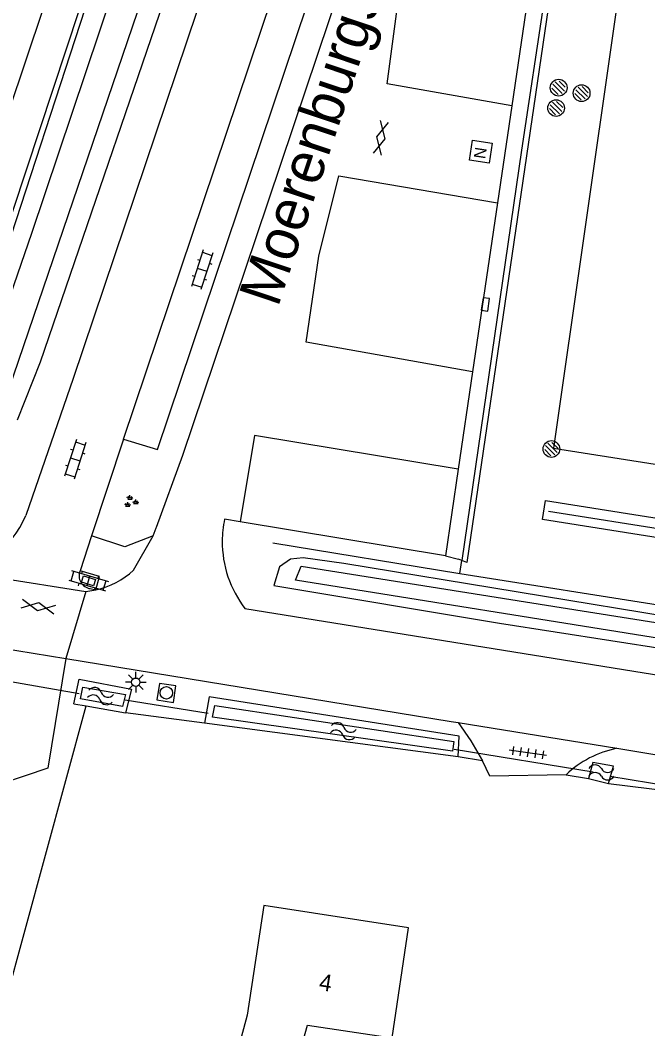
# Model space of a CAD drawing. Extents: x 135999 to 138000, y 396000 to 398501.
# Drawn here: x 136337.3 to 136374.9, y 396332.1 to 396392.4 of the extents above; entities that cross this region are included whole.
import ezdxf

# ---------------------------------------------------------------- set-up
doc = ezdxf.new("R2010")
doc.units = 0
for name, color, linetype in [('bs-afsc-ballenvanger', 7, 'Continuous'), ('bs-afsc-belijning', 7, 'Continuous'), ('bs-afsc-hekwerk laag', 7, 'Continuous'), ('bs-symb-cornervlag', 7, 'Continuous'), ('bs-symb-magneetklep', 7, 'Continuous'), ('bs-symb-sproeier', 7, 'Continuous'), ('gg-afsc-draadraster', 7, 'Continuous'), ('gg-afsc-hekwerk', 7, 'Continuous'), ('gg-afsc-lijn draadraster', 7, 'Continuous'), ('gg-anno-huisnummerreeks BGT', 7, 'Continuous'), ('gg-anno-openbare ruimte label', 7, 'Continuous'), ('gg-bbg-hoofdgebouw', 7, 'Continuous'), ('gg-knt-verharding', 7, 'Continuous'), ('gg-knt-verharding nz', 7, 'Continuous'), ('gg-kntw-bovenkant insteek waterloop', 7, 'Continuous'), ('gg-kntw-waterlijn', 7, 'Continuous'), ('gg-kwrk-duiker nz buis', 7, 'Continuous'), ('gt-grn-groengrens', 7, 'Continuous'), ('gt-grn-weggrens', 7, 'Continuous'), ('gt-symb-gesloten verharding', 7, 'Continuous'), ('gt-symb-groenvak', 7, 'Continuous'), ('gt-symb-klinker verharding', 7, 'Continuous'), ('gt-symb-kolk', 7, 'Continuous'), ('gt-symb-kolk center center', 7, 'Continuous'), ('gt-symb-lichtmast', 7, 'Continuous'), ('gt-symb-nortonput', 7, 'Continuous'), ('gt-symb-rioolschacht', 7, 'Continuous'), ('gt-symb-tegel verharding', 7, 'Continuous'), ('gt-symb-watersymbool', 7, 'Continuous')]:
    doc.layers.add(name, color=color, linetype=linetype)

# ---------------------------------------------------------------- blocks, each defined once
blk = doc.blocks.new('gt0-KL1')
at = {"layer": 'gt-symb-klinker verharding'}
for p, q in [((-1.15, 0.3), (1.15, 0.3)), ((-1, -0.3), (-1, 0.3)), ((-0.5, 0.3), (-0.5, 0.45)), ((0, -0.3), (0, 0.3)), ((0.5, 0.3), (0.5, 0.45)), ((1, -0.3), (1, 0.3)), ((-1.15, -0.3), (1.15, -0.3)), ((-0.5, -0.45), (-0.5, -0.3)), ((0.5, -0.45), (0.5, -0.3))]:
    blk.add_line(p, q, dxfattribs=at)
blk = doc.blocks.new('gt0-GESVH1')
at = {"layer": 'gt-symb-gesloten verharding'}
for p, q in [((-0.992, -0.261), (0.008, 0.239)), ((0.008, -0.261), (-0.992, 0.239)), ((0.008, 0.239), (1.008, -0.261)), ((1.008, 0.239), (0.008, -0.261))]:
    blk.add_line(p, q, dxfattribs=at)
blk = doc.blocks.new('gt0-NPUT')
at = {"layer": 'gt-symb-nortonput'}
blk.add_lwpolyline([(-0.566, -0.608), (-0.566, 0.592), (0.634, 0.592), (0.634, -0.608)], close=True, dxfattribs=at)
blk.add_text('N', height=0.7, dxfattribs=at).set_placement((-0.221, -0.381))
blk = doc.blocks.new('gt0-KOLK')
at = {"layer": 'gt-symb-kolk'}
blk.add_lwpolyline([(0, 0), (0.375, 0), (0.375, 0.4), (-0.375, 0.4), (-0.375, 0), (0, 0)], dxfattribs=at)
blk = doc.blocks.new('bs0-CORNVLG')
at = {"layer": 'bs-symb-cornervlag'}
for p, q in [((-0.345, 0.203), (0.203, -0.345)), ((-0.212, 0.354), (0.345, -0.203)), ((0.025, 0.399), (0.399, 0.025)), ((-0.399, -0.025), (-0.025, -0.399))]:
    blk.add_line(p, q, dxfattribs=at)
blk.add_circle((0, 0), 0.5, dxfattribs=at)
blk = doc.blocks.new('BS0-MAGNKLP')
at = {"layer": 'bs-symb-magneetklep'}
for p, q in [((-0.345, 0.203), (0.203, -0.345)), ((-0.212, 0.354), (0.345, -0.203)), ((0.025, 0.399), (0.399, 0.025)), ((-0.399, -0.025), (-0.025, -0.399))]:
    blk.add_line(p, q, dxfattribs=at)
blk.add_circle((0, 0), 0.5, dxfattribs=at)
blk = doc.blocks.new('bs0-SPROEIER')
at = {"layer": 'bs-symb-sproeier'}
for p, q in [((-0.345, 0.203), (0.203, -0.345)), ((-0.212, 0.354), (0.345, -0.203)), ((0.025, 0.399), (0.399, 0.025)), ((-0.399, -0.025), (-0.025, -0.399))]:
    blk.add_line(p, q, dxfattribs=at)
blk.add_circle((0, 0), 0.5, dxfattribs=at)
blk = doc.blocks.new('gt0-KOLKCC')
at = {"layer": 'gt-symb-kolk center center'}
blk.add_lwpolyline([(-0.375, 0.2), (0.375, 0.2), (0.375, -0.2), (-0.375, -0.2)], close=True, dxfattribs=at)
blk = doc.blocks.new('gt0-GRVAK')
at = {"layer": 'gt-symb-groenvak'}
for p, q in [((-0.11, 0.189), (-0.228, 0.24)), ((-0.182, 0.153), (0.088, 0.153)), ((-0.091, 0.211), (-0.156, 0.322)), ((-0.047, 0.214), (-0.047, 0.393)), ((-0.004, 0.211), (0.061, 0.322)), ((0.015, 0.189), (0.133, 0.24)), ((0.262, -0.052), (0.197, 0.059)), ((0.305, -0.049), (0.305, 0.13)), ((0.349, -0.052), (0.414, 0.059)), ((-0.245, -0.228), (-0.363, -0.177)), ((-0.318, -0.264), (-0.047, -0.264)), ((-0.226, -0.206), (-0.291, -0.095)), ((-0.183, -0.203), (-0.183, -0.024)), ((-0.139, -0.206), (-0.074, -0.095)), ((-0.12, -0.228), (-0.002, -0.177)), ((0.243, -0.074), (0.125, -0.023)), ((0.17, -0.11), (0.441, -0.11)), ((0.368, -0.074), (0.486, -0.023))]:
    blk.add_line(p, q, dxfattribs=at)
blk = doc.blocks.new('gt0-TEG1')
at = {"layer": 'gt-symb-tegel verharding'}
for p, q in [((-1.125, 0), (1.125, 0)), ((-0.9, -0.25), (-0.9, 0.25)), ((-0.45, -0.25), (-0.45, 0.25)), ((0, -0.25), (0, 0.25)), ((0.45, -0.25), (0.45, 0.25)), ((0.9, -0.25), (0.9, 0.25))]:
    blk.add_line(p, q, dxfattribs=at)
blk = doc.blocks.new('gt0-WA')
at = {"layer": 'gt-symb-watersymbool'}
for centre, start, end in [((-0.323, 0.022), 28.07249, 151.92751), ((0.427, 0.422), 208.07248, 331.92751), ((-0.323, -0.428), 28.07249, 151.92751), ((0.427, -0.028), 208.07248, 331.92751)]:
    blk.add_arc(centre, 0.425, start, end, dxfattribs=at)
blk = doc.blocks.new('gt0-RS')
at = {"layer": 'gt-symb-rioolschacht'}
blk.add_lwpolyline([(-0.5, -0.5), (0.5, -0.5), (0.5, 0.5), (-0.5, 0.5)], close=True, dxfattribs=at)
blk.add_circle((0, 0), 0.375, dxfattribs=at)
blk = doc.blocks.new('gt0-LMAST')
at = {"layer": 'gt-symb-lichtmast'}
for p, q in [((-0.005, 0.246), (-0.005, 0.621)), ((-0.182, 0.173), (-0.447, 0.438)), ((0.172, 0.173), (0.437, 0.438)), ((-0.255, -0.004), (-0.63, -0.004)), ((-0.182, -0.181), (-0.447, -0.446)), ((-0.005, -0.254), (-0.005, -0.629)), ((0.437, -0.446), (0.172, -0.181)), ((0.245, -0.004), (0.62, -0.004))]:
    blk.add_line(p, q, dxfattribs=at)
blk.add_circle((-0.005, -0.004), 0.25, dxfattribs=at)

msp = doc.modelspace()

# ---------------------------------------------------------------- linework, layer by layer
at = {"layer": 'bs-afsc-ballenvanger'}
msp.add_line((136369.803, 396400.981), (136367.356, 396384.632), dxfattribs=at)
at = {"layer": 'bs-afsc-belijning'}
msp.add_lwpolyline([(136378.402, 396430.675), (136369.254, 396366.811), (136467.634, 396351.324), (136477.189, 396415.479), (136378.402, 396430.675)], dxfattribs=at)
at = {"layer": 'bs-afsc-hekwerk laag'}
msp.add_line((136368.955, 396363.037), (136408.299, 396356.817), dxfattribs=at)
at = {"layer": 'gg-afsc-draadraster'}
msp.add_lwpolyline([(136316.473, 396371.328), (136328.234, 396369.556), (136330.28, 396369.629), (136330.708, 396369.968), (136331.376, 396371.258), (136340.864, 396399.461), (136351.225, 396430.408), (136351.461, 396433.69), (136351.292, 396436.582), (136350.934, 396439.456), (136350.145, 396442.255), (136346.234, 396453.511)], dxfattribs=at)
at = {"layer": 'gg-afsc-hekwerk'}
for p, q in [((136369.803, 396400.981), (136367.356, 396384.632)), ((136367.356, 396384.632), (136363.778, 396360.091)), ((136368.955, 396363.037), (136408.299, 396356.817)), ((136352.472, 396361.146), (136363.662, 396359.3)), ((136363.662, 396359.3), (136363.778, 396360.091)), ((136363.662, 396359.3), (136422.054, 396350.081)), ((136336.431, 396333.512), (136341.298, 396351.385)), ((136336.431, 396333.512), (136341.298, 396351.385))]:
    msp.add_line(p, q, dxfattribs=at)
at = {"layer": 'gg-afsc-lijn draadraster'}
msp.add_lwpolyline([(136315.547, 396371.468), (136328.234, 396369.556), (136330.28, 396369.629), (136330.708, 396369.968), (136331.376, 396371.258), (136340.864, 396399.461), (136351.225, 396430.408), (136351.461, 396433.69), (136351.292, 396436.582), (136350.934, 396439.456), (136350.145, 396442.255), (136346.234, 396453.511), (136318.123, 396443.287), (136292.891, 396434.111)], dxfattribs=at)
at = {"layer": 'gg-bbg-hoofdgebouw'}
for points in [[(136360.59, 396338.11), (136351.93, 396339.45), (136350.92, 396332.88), (136349.45, 396327.4), (136345.05, 396328.65)], [(136353.15, 396305.594), (136358.514, 396324.838), (136352.897, 396326.435), (136354.542, 396332.282), (136359.606, 396331.525), (136360.59, 396338.11)]]:
    msp.add_lwpolyline(points, dxfattribs=at)
at = {"layer": 'gg-knt-verharding'}
for p, q in [((136366.763, 396387.286), (136365.91, 396381.49)), ((136365.91, 396381.49), (136364.42, 396371.371)), ((136364.42, 396371.371), (136363.562, 396365.543)), ((136343.534, 396367.348), (136341.622, 396361.556)), ((136363.562, 396365.543), (136362.799, 396360.358)), ((136350.513, 396362.395), (136349.575, 396362.551)), ((136362.799, 396360.358), (136350.513, 396362.395)), ((136345.305, 396361.555), (136345.481, 396362.033)), ((136345.481, 396362.033), (136345.494, 396362.069)), ((136341.622, 396361.556), (136340.932, 396359.464)), ((136344.124, 396359.512), (136345.305, 396361.555)), ((136362.799, 396360.358), (136363.573, 396360.173)), ((136363.778, 396360.091), (136363.573, 396360.173)), ((136332.689, 396359.581), (136341.283, 396358.222)), ((136341.283, 396358.222), (136341.868, 396358.331)), ((136341.542, 396358.4), (136341.868, 396358.331)), ((136336.158, 396354.863), (136340.08, 396354.222)), ((136363.552, 396350.388), (136373.06, 396348.846)), ((136373.06, 396348.846), (136377.113, 396348.189))]:
    msp.add_line(p, q, dxfattribs=at)
for points in [[(136351.498, 396379.478), (136369.019, 396431.609), (136369.594, 396433.811), (136370.02, 396436.047)], [(136444.613, 396425.394), (136483.556, 396419.306), (136483.359, 396418.079), (136375.706, 396435.008), (136375.007, 396434.485), (136364.072, 396359.973), (136363.778, 396360.091)], [(136360.876, 396431.432), (136340.51, 396370.978), (136337.676, 396362.774)], [(136343.534, 396367.348), (136345.554, 396366.721), (136366.957, 396430.277)], [(136371.188, 396417.185), (136368.898, 396401.792), (136366.763, 396387.286)], [(136345.494, 396362.069), (136347.082, 396366.382), (136351.498, 396379.478)], [(136368.608, 396362.538), (136368.781, 396363.669), (136407.694, 396357.508), (136407.822, 396358.302), (136413.208, 396357.336), (136413.118, 396356.595), (136420.535, 396355.482), (136420.612, 396355.977), (136426.028, 396354.998), (136425.966, 396354.621), (136464.689, 396348.467), (136464.493, 396347.39), (136425.771, 396353.51), (136425.75, 396353.01), (136420.241, 396353.979), (136420.294, 396354.342), (136368.608, 396362.538)], [(136341.868, 396358.331), (136342.098, 396359.126), (136340.932, 396359.464)], [(136350.799, 396357.209), (136385.344, 396351.652), (136429.378, 396344.684), (136470.073, 396338.203), (136496.298, 396334.058), (136506.466, 396332.412)], [(136340.08, 396354.222), (136339.007, 396347.648), (136334.85, 396346.267)], [(136340.08, 396354.222), (136363.13, 396350.456), (136363.552, 396350.388)], [(136363.552, 396350.388), (136364.32, 396349.287), (136365.008, 396348.091)], [(136370.012, 396347.265), (136365.455, 396347.17), (136365.008, 396348.091)]]:
    msp.add_lwpolyline(points, dxfattribs=at)
for centre, radius, start, end in [((136332.948, 396364.667), 5.093, 267.08221, 338.17779), ((136355.998, 396361.217), 6.56, 168.26644, 179.72929), ((136356.004, 396361.212), 6.566, 179.68338, 217.56061), ((136341.646, 396359.167), 0.774, 157.40271, 262.2493), ((136340.963, 396362.805), 4.565, 281.43638, 313.82709), ((136374.316, 396342.695), 6.278, 101.54457, 133.28704)]:
    msp.add_arc(centre, radius, start, end, dxfattribs=at)
at = {"layer": 'gg-knt-verharding nz'}
for p, q in [((136343.534, 396367.348), (136364.941, 396430.964)), ((136356.414, 396383.109), (136365.91, 396381.49))]:
    msp.add_line(p, q, dxfattribs=at)
for points in [[(136366.763, 396387.286), (136359.308, 396388.614), (136359.993, 396393.706), (136362.489, 396393.37), (136364.718, 396408.071)], [(136364.42, 396371.371), (136354.458, 396373.14), (136355.217, 396378.298), (136356.414, 396383.109)], [(136363.562, 396365.543), (136351.371, 396367.565), (136350.513, 396362.395)]]:
    msp.add_lwpolyline(points, dxfattribs=at)
at = {"layer": 'gg-kntw-bovenkant insteek waterloop'}
for p, q in [((136340.565, 396351.515), (136341.298, 396351.385)), ((136341.298, 396351.385), (136343.647, 396350.967)), ((136363.55, 396348.332), (136348.38, 396350.341)), ((136371.358, 396347.043), (136372.552, 396346.737))]:
    msp.add_line(p, q, dxfattribs=at)
for points in [[(136353.609, 396430.235), (136352.783, 396426.924), (136344.17, 396402.155), (136333.229, 396368.651)], [(136337.187, 396368.492), (136338.555, 396371.978), (136347.487, 396398.048), (136356.535, 396425.934)], [(136354.29, 396360.247), (136353.513, 396360.156), (136352.86, 396359.695), (136352.516, 396358.594), (136366.034, 396356.326), (136389.348, 396352.705), (136419.783, 396347.744), (136420.445, 396347.691), (136420.933, 396348.011), (136421.368, 396348.95), (136421.378, 396349.72), (136414.825, 396350.555), (136377.587, 396356.476), (136356.724, 396359.898), (136354.29, 396360.247)], [(136340.565, 396351.515), (136340.881, 396352.989), (136344.011, 396352.394), (136343.647, 396350.967)], [(136363.55, 396348.332), (136363.614, 396349.573), (136348.65, 396351.931), (136348.38, 396350.341)], [(136372.552, 396346.737), (136372.85, 396347.782), (136371.611, 396347.992), (136371.358, 396347.043)]]:
    msp.add_lwpolyline(points, dxfattribs=at)
at = {"layer": 'gg-kntw-waterlijn'}
for points in [[(136334.096, 396368.616), (136334.428, 396369.23), (136338.045, 396379.666), (136353.432, 396425.44), (136354.533, 396428.714), (136355.099, 396432.023), (136355.308, 396435.146), (136354.346, 396441.911), (136353.18, 396445.343), (136349.683, 396453.889), (136351.539, 396454.649), (136355.718, 396443.529), (136356.255, 396441.231), (136356.884, 396435.899), (136356.827, 396432.547), (136356.002, 396428.006), (136354.137, 396421.607), (136336.02, 396368.539)], [(136354.153, 396359.749), (136369.725, 396357.273), (136390.367, 396353.992), (136419.957, 396348.985), (136420.536, 396348.886), (136420.403, 396348.101), (136405.798, 396350.572), (136376.23, 396355.313), (136353.83, 396358.905), (136354.153, 396359.749)], [(136341.085, 396352.499), (136343.658, 396352.058), (136343.472, 396351.355), (136340.948, 396351.809), (136341.085, 396352.499)], [(136348.985, 396351.4), (136363.3, 396349.248), (136363.216, 396348.683), (136348.855, 396350.703), (136348.985, 396351.4)]]:
    msp.add_lwpolyline(points, dxfattribs=at)
at = {"layer": 'gg-kwrk-duiker nz buis'}
for p, q in [((136340.87, 396352.106), (136335.001, 396353.146)), ((136348.59, 396350.927), (136343.62, 396351.729)), ((136371.634, 396347.409), (136363.315, 396348.771)), ((136384.4, 396345.208), (136372.631, 396347.154))]:
    msp.add_line(p, q, dxfattribs=at)
at = {"layer": 'gt-grn-groengrens'}
for p, q in [((136348.38, 396350.341), (136343.647, 396350.967)), ((136365.008, 396348.091), (136363.55, 396348.332)), ((136370.012, 396347.265), (136371.358, 396347.043)), ((136372.552, 396346.737), (136376.488, 396346.262))]:
    msp.add_line(p, q, dxfattribs=at)
for points in [[(136346.234, 396453.511), (136347.975, 396454.225), (136352.724, 396439.157), (136353.353, 396433.866), (136352.766, 396429.008), (136332.936, 396369.082), (136332.252, 396368.015), (136331.112, 396367.428), (136329.627, 396367.216), (136328.525, 396367.311), (136319.114, 396368.781), (136318.906, 396369.512), (136316.249, 396369.841), (136316.473, 396371.328)], [(136345.305, 396361.555), (136343.61, 396360.9), (136341.622, 396361.556)]]:
    msp.add_lwpolyline(points, dxfattribs=at)
at = {"layer": 'gt-grn-weggrens'}
msp.add_line((136341.283, 396358.222), (136340.08, 396354.222), dxfattribs=at)

# ---------------------------------------------------------------- block references
at = {"layer": 'bs-symb-cornervlag'}
msp.add_blockref('bs0-CORNVLG', (136369.136, 396366.755), dxfattribs=at)
at = {"layer": 'bs-symb-magneetklep'}
for p in [(136369.572, 396388.376), (136369.417, 396387.156)]:
    msp.add_blockref('BS0-MAGNKLP', p, dxfattribs=at)
at = {"layer": 'bs-symb-sproeier'}
msp.add_blockref('bs0-SPROEIER', (136370.947, 396388.047), dxfattribs=at)
at = {"layer": 'gt-symb-gesloten verharding'}
for p, rotation in [((136358.915, 396385.367), 77.82524886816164), ((136338.42, 396357.335), -10.197205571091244)]:
    msp.add_blockref('gt0-GESVH1', p, dxfattribs=dict(at, rotation=rotation))
at = {"layer": 'gt-symb-groenvak'}
msp.add_blockref('gt0-GRVAK', (136343.963, 396363.604), dxfattribs=at)
at = {"layer": 'gt-symb-klinker verharding'}
for p, rotation in [((136348.228, 396377.484), -107.87342106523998), ((136340.639, 396366.134), -107.87342106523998), ((136341.439, 396358.868), -16.13420459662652)]:
    msp.add_blockref('gt0-KL1', p, dxfattribs=dict(at, rotation=rotation))
at = {"layer": 'gt-symb-kolk', "rotation": -98.34086686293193}
msp.add_blockref('gt0-KOLK', (136364.99, 396375.438), dxfattribs=at)
at = {"layer": 'gt-symb-kolk center center', "rotation": -16.02410965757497}
msp.add_blockref('gt0-KOLKCC', (136341.435, 396358.868), dxfattribs=at)
at = {"layer": 'gt-symb-lichtmast'}
msp.add_blockref('gt0-LMAST', (136344.269, 396352.807), dxfattribs=at)
at = {"layer": 'gt-symb-nortonput', "rotation": -98.68085058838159}
msp.add_blockref('gt0-NPUT', (136364.927, 396384.579), dxfattribs=at)
at = {"layer": 'gt-symb-rioolschacht', "rotation": -98.74616226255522}
msp.add_blockref('gt0-RS', (136346.093, 396352.163), dxfattribs=at)
at = {"layer": 'gt-symb-tegel verharding', "rotation": 171.8374905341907}
msp.add_blockref('gt0-TEG1', (136367.729, 396348.582), dxfattribs=at)
at = {"layer": 'gt-symb-watersymbool'}
for p, rotation in [((136342.108, 396351.979), -10.074332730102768), ((136356.633, 396349.883), -8.972626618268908)]:
    msp.add_blockref('gt0-WA', p, dxfattribs=dict(at, rotation=rotation))
msp.add_blockref('gt0-WA', (136372.074, 396347.406), dxfattribs=at)

# ---------------------------------------------------------------- texts
at = {"layer": 'gg-anno-huisnummerreeks BGT'}
msp.add_text('4', height=1, rotation=351.2, dxfattribs=at).set_placement((136355.188, 396334.392))
at = {"layer": 'gg-anno-openbare ruimte label'}
msp.add_text('Moerenburgseweg', height=2.5, rotation=71.5, dxfattribs=at).set_placement((136352.766, 396375.185))

doc.saveas('drawing.dxf')
